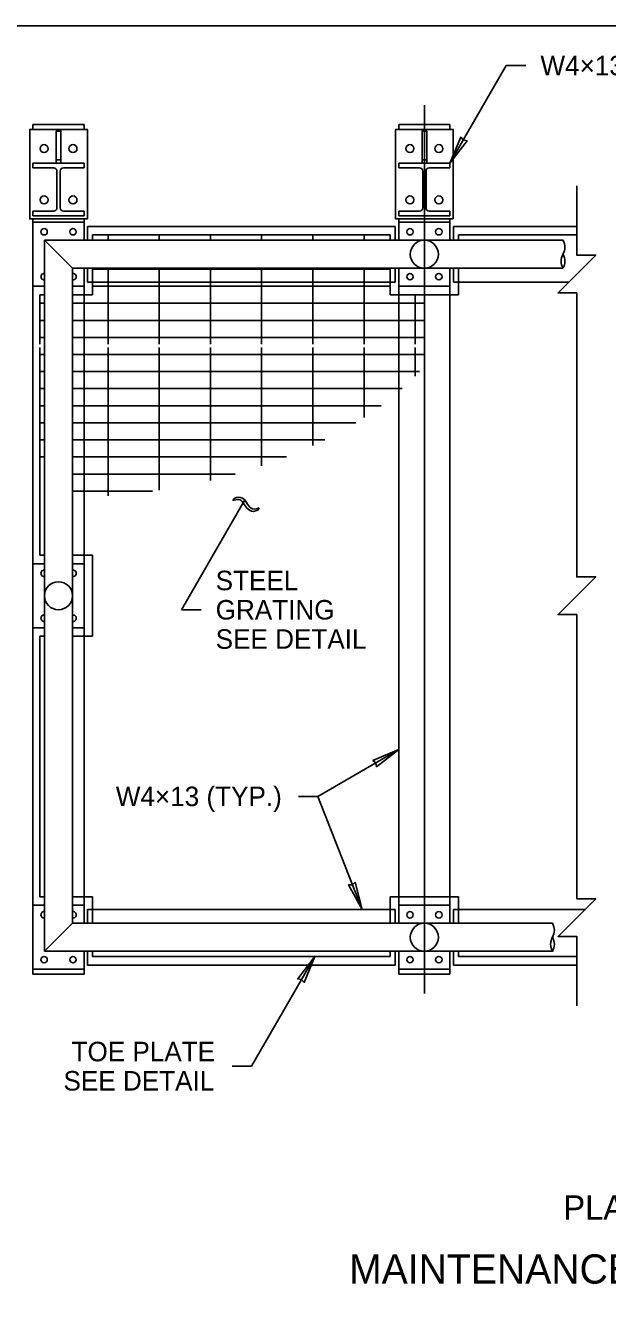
# Model space of a CAD drawing. Extents: x 99862 to 103151, y 100000 to 108076.
# Drawn here: x 100986 to 101463, y 101023 to 102076 of the extents above; entities that cross this region are included whole.
import ezdxf

# ---------------------------------------------------------------- set-up
doc = ezdxf.new("R2010")
doc.units = 0
for name, color, linetype in [('Level 1', 7, 'Continuous'), ('Level 13', 7, 'Continuous'), ('Level 15', 7, 'Continuous'), ('Level 20', 7, 'Continuous'), ('Level 36', 7, 'Continuous'), ('Level 4', 7, 'Continuous'), ('Level 5', 7, 'Continuous')]:
    doc.layers.add(name, color=color, linetype=linetype)

msp = doc.modelspace()

# ---------------------------------------------------------------- linework, layer by layer
at = {"layer": 'Level 1'}
msp.add_lwpolyline([(99862, 99999.5), (103151, 99999.5), (103151, 102075.5), (99862, 102075.5)], close=True, dxfattribs=at)
at = {"layer": 'Level 13'}
for p, q in [((100991.8, 101994.4), (101033.8, 101994.4)), ((100991.8, 101990.5), (100991.8, 101994.4)), ((101033.8, 101990.5), (101033.8, 101994.4)), ((101291.8, 101994.4), (101333.8, 101994.4)), ((101291.8, 101990.5), (101291.8, 101994.4)), ((101333.8, 101990.5), (101333.8, 101994.4)), ((101033.8, 101962.9), (100991.8, 101962.9)), ((100991.8, 101962.9), (100991.8, 101959)), ((100991.8, 101959), (101008.9, 101959)), ((101011.5, 101956.3), (101011.5, 101926.1)), ((101014.2, 101926.1), (101014.2, 101956.3)), ((101016.8, 101959), (101033.8, 101959)), ((101033.8, 101959), (101033.8, 101962.9)), ((101333.8, 101962.9), (101291.8, 101962.9)), ((101291.8, 101962.9), (101291.8, 101959)), ((101291.8, 101959), (101308.9, 101959)), ((101311.5, 101956.3), (101311.5, 101926.1)), ((101314.2, 101926.1), (101314.2, 101956.3)), ((101316.8, 101959), (101333.8, 101959)), ((101333.8, 101959), (101333.8, 101962.9)), ((101008.9, 101923.5), (100991.8, 101923.5)), ((100991.8, 101923.5), (100991.8, 101919.6)), ((101033.8, 101923.5), (101016.8, 101923.5)), ((101033.8, 101919.6), (101033.8, 101923.5)), ((101308.9, 101923.5), (101291.8, 101923.5)), ((101291.8, 101923.5), (101291.8, 101919.6)), ((101333.8, 101923.5), (101316.8, 101923.5)), ((101333.8, 101919.6), (101333.8, 101923.5)), ((100991.8, 101919.6), (101033.8, 101919.6)), ((100991.8, 101914.3), (101033.8, 101914.3)), ((101291.8, 101919.6), (101333.8, 101919.6)), ((101291.8, 101914.3), (101333.8, 101914.3)), ((101001.3, 101861.8), (100991.8, 101861.8)), ((101033.8, 101861.8), (101024.3, 101861.8)), ((101333.8, 101861.8), (101291.8, 101861.8)), ((100991.8, 101634.3), (101001.3, 101634.3)), ((101024.3, 101634.3), (101033.8, 101634.3)), ((101001.3, 101581.8), (100991.8, 101581.8)), ((101033.8, 101581.8), (101024.3, 101581.8)), ((100991.8, 101301.8), (100991.8, 101354.3)), ((100991.8, 101354.3), (101001.3, 101354.3)), ((101024.3, 101354.3), (101033.8, 101354.3)), ((101033.8, 101354.3), (101033.8, 101339.6)), ((101033.8, 101316.6), (101033.8, 101301.8)), ((101033.8, 101301.8), (100991.8, 101301.8))]:
    msp.add_line(p, q, dxfattribs=at)
for points in [[(101036.5, 101917), (100989.2, 101917), (100989.2, 101990.5), (101036.5, 101990.5)], [(101010.9, 101962.9), (101010.9, 101989.1), (101014.8, 101989.1), (101014.8, 101962.9)], [(101336.5, 101917), (101289.2, 101917), (101289.2, 101990.5), (101336.5, 101990.5)], [(101310.9, 101962.9), (101310.9, 101989.1), (101314.8, 101989.1), (101314.8, 101962.9)], [(101010.9, 101962.9), (101010.9, 101965.5), (101014.8, 101965.5), (101014.8, 101962.9)], [(101310.9, 101962.9), (101310.9, 101965.5), (101314.8, 101965.5), (101314.8, 101962.9)]]:
    msp.add_lwpolyline(points, close=True, dxfattribs=at)
for points in [[(101291.8, 101339.6), (101291.8, 101354.3), (101333.8, 101354.3), (101333.8, 101339.6)], [(101333.8, 101316.6), (101333.8, 101301.8), (101291.8, 101301.8), (101291.8, 101316.6)]]:
    msp.add_lwpolyline(points, dxfattribs=at)
for centre, radius in [((101001, 101974.7), 3.28), ((101024.7, 101974.7), 3.28), ((101301, 101974.7), 3.28), ((101324.7, 101974.7), 3.28), ((101001, 101932.7), 3.28), ((101024.7, 101932.7), 3.28), ((101301, 101932.7), 3.28), ((101324.7, 101932.7), 3.28), ((101001, 101906.5), 2.62), ((101024.7, 101906.5), 2.62), ((101301, 101906.5), 2.62), ((101324.7, 101906.5), 2.62), ((101301, 101869.7), 2.62), ((101324.7, 101869.7), 2.62), ((101301, 101346.5), 2.62), ((101324.7, 101346.5), 2.62), ((101001, 101309.7), 2.62), ((101024.7, 101309.7), 2.62), ((101301, 101309.7), 2.62), ((101324.7, 101309.7), 2.62)]:
    msp.add_circle(centre, radius, dxfattribs=at)
for centre, start, end in [((101008.9, 101956.3), 0, 90), ((101016.8, 101956.3), 90, 180), ((101308.9, 101956.3), 0, 90), ((101316.8, 101956.3), 90, 180), ((101008.9, 101926.1), 270, 360), ((101016.8, 101926.1), 180, 270), ((101308.9, 101926.1), 270, 360), ((101316.8, 101926.1), 180, 270), ((101001, 101869.7), 83.163, 276.837), ((101024.7, 101869.7), 263.1627, 96.8373), ((101001, 101626.5), 83.1632, 276.8368), ((101024.7, 101626.5), 263.1625, 96.8375), ((101001, 101589.7), 83.1632, 276.8368), ((101024.7, 101589.7), 263.1625, 96.8375), ((101001, 101346.5), 83.1632, 276.8368), ((101024.7, 101346.5), 263.1625, 96.8375)]:
    msp.add_arc(centre, 2.62, start, end, dxfattribs=at)
at = {"layer": 'Level 15'}
for p, q in [((101333.8, 101962.9), (101380, 102042.8)), ((101380, 102042.8), (101396, 102042.8)), ((101312.8, 101281.9), (101312.8, 102010.4)), ((101165.6, 101686.6), (101113.7, 101596.6)), ((101113.7, 101596.6), (101129.7, 101596.6)), ((101225.5, 101443.5), (101291.8, 101481.9)), ((101209.5, 101443.5), (101225.5, 101443.5)), ((101225.5, 101443.5), (101261.7, 101350.9)), ((101223, 101312.3), (101171.1, 101222.3)), ((101171.1, 101222.3), (101155.1, 101222.3))]:
    msp.add_line(p, q, dxfattribs=at)
for points in [[(101333.8, 101962.9), (101347.8, 101981.2), (101344.7, 101981.8), (101342.7, 101984.2)], [(101291.8, 101481.9), (101270.6, 101473), (101273, 101471), (101273.6, 101467.9)], [(101261.7, 101350.9), (101256.2, 101373.2), (101253.8, 101371.1), (101250.6, 101371)], [(101223, 101312.3), (101214.2, 101291), (101212.1, 101293.4), (101209, 101294)]]:
    msp.add_lwpolyline(points, close=True, dxfattribs=at)
msp.add_lwpolyline([(101437.8, 101271.9), (101437.8, 101328.8), (101422.4, 101328.8), (101453.3, 101359.7), (101437.8, 101359.7), (101437.8, 101592.6), (101422.4, 101592.6), (101453.3, 101623.6), (101437.8, 101623.6), (101437.8, 101856.4), (101422.4, 101856.4), (101453.3, 101887.4), (101437.8, 101887.4), (101437.8, 101944.2)], dxfattribs=at)
for centre, start, end in [((101416.5, 101893.8), 330, 30), ((101436.5, 101882.3), 150, 210), ((101416.5, 101882.3), 330, 30), ((101407.9, 101333.8), 330, 30), ((101427.8, 101322.3), 150, 210), ((101407.9, 101322.3), 330, 30)]:
    msp.add_arc(centre, 11.5, start, end, dxfattribs=at)
at = {"layer": 'Level 20'}
for p, q in [((101155.7, 101686.1), (101156.8, 101687.9)), ((101159.3, 101687), (101155.7, 101686.1)), ((101156.8, 101687.9), (101158.8, 101688.7)), ((101158.8, 101688.7), (101160.5, 101688.9)), ((101160.9, 101686.9), (101159.3, 101687)), ((101160.5, 101688.9), (101162.1, 101688.7)), ((101162.3, 101686.5), (101160.9, 101686.9)), ((101162.1, 101688.7), (101163.7, 101688.1)), ((101163.4, 101685.5), (101162.3, 101686.5)), ((101164.8, 101683.5), (101163.4, 101685.5)), ((101163.7, 101688.1), (101165.6, 101686.6)), ((101167.3, 101679.9), (101164.8, 101683.5)), ((101165.6, 101686.6), (101167.9, 101683.2)), ((101169.4, 101678.2), (101167.3, 101679.9)), ((101167.9, 101683.2), (101169.3, 101681.1)), ((101169.3, 101681.1), (101170.8, 101679.8)), ((101170.8, 101679.8), (101172, 101679.3)), ((101172, 101679.3), (101173.4, 101679.2)), ((101173.4, 101679.2), (101175.1, 101679.4)), ((101175.1, 101679.4), (101177.4, 101680.2)), ((101177.4, 101680.2), (101176.3, 101678.3)), ((101171, 101677.5), (101169.4, 101678.2)), ((101172.7, 101677.3), (101171, 101677.5)), ((101174.5, 101677.6), (101172.7, 101677.3)), ((101176.3, 101678.3), (101174.5, 101677.6))]:
    msp.add_line(p, q, dxfattribs=at)
at = {"layer": 'Level 36'}
for centre in [(101312.8, 101888.1), (101012.8, 101608.1), (101312.8, 101328.1)]:
    msp.add_circle(centre, 11.5, dxfattribs=at)
at = {"layer": 'Level 4'}
for p, q in [((100991.8, 101990.5), (100991.8, 101994.4)), ((100991.8, 101994.4), (101033.8, 101994.4)), ((101033.8, 101994.4), (101033.8, 101990.5)), ((101291.8, 101990.5), (101291.8, 101994.4)), ((101291.8, 101994.4), (101333.8, 101994.4)), ((101333.8, 101994.4), (101333.8, 101990.5)), ((100991.8, 101297.9), (100991.8, 101917)), ((101033.8, 101899.6), (101033.8, 101917)), ((101036.6, 101910.9), (101289, 101910.9)), ((101036.6, 101910.9), (101036.6, 101899.6)), ((101289, 101910.9), (101289, 101899.6)), ((101291.8, 101917), (101291.8, 101899.6)), ((101333.8, 101917), (101333.8, 101899.6)), ((101437.8, 101910.9), (101336.6, 101910.9)), ((101336.6, 101899.6), (101336.6, 101910.9)), ((101040.8, 101903.9), (101284.8, 101903.9)), ((101040.8, 101903.9), (101040.8, 101899.6)), ((101053.4, 101903.9), (101053.4, 101899.6)), ((101095.4, 101903.9), (101095.4, 101899.6)), ((101137.4, 101903.9), (101137.4, 101899.6)), ((101179.4, 101903.9), (101179.4, 101899.6)), ((101221.4, 101903.9), (101221.4, 101899.6)), ((101263.4, 101903.9), (101263.4, 101899.6)), ((101284.8, 101903.9), (101284.8, 101899.6)), ((101340.8, 101903.9), (101437.8, 101903.9)), ((101340.8, 101903.9), (101340.8, 101899.6)), ((101033.8, 101339.6), (101033.8, 101876.6)), ((101036.6, 101876.6), (101036.6, 101865.3)), ((101040.8, 101876.6), (101040.8, 101854.9)), ((101040.8, 101875.9), (101284.8, 101875.9)), ((101053.4, 101876.6), (101053.4, 101814.3)), ((101095.4, 101876.6), (101095.4, 101814.3)), ((101137.4, 101876.6), (101137.4, 101814.3)), ((101179.4, 101876.6), (101179.4, 101814.3)), ((101221.4, 101876.6), (101221.4, 101814.3)), ((101263.4, 101876.6), (101263.4, 101814.3)), ((101284.8, 101876.6), (101284.8, 101854.9)), ((101289, 101876.6), (101289, 101865.3)), ((101291.8, 101876.6), (101291.8, 101339.6)), ((101333.8, 101876.6), (101333.8, 101339.6)), ((101336.6, 101865.3), (101336.6, 101876.6)), ((101340.8, 101876.6), (101340.8, 101854.9)), ((101036.6, 101865.3), (101289, 101865.3)), ((101040.8, 101861.9), (101284.8, 101861.9)), ((101431.2, 101865.3), (101336.6, 101865.3)), ((100997.4, 101854.9), (100997.4, 101814.3)), ((100997.4, 101854.9), (101001.3, 101854.9)), ((100997.4, 101847.9), (101001.3, 101847.9)), ((101024.3, 101854.9), (101040.8, 101854.9)), ((101024.3, 101847.9), (101312.8, 101847.9)), ((101340.8, 101854.9), (101284.8, 101854.9)), ((101305.4, 101854.9), (101305.4, 101814.3)), ((100997.4, 101833.9), (101001.3, 101833.9)), ((101024.3, 101833.9), (101312.8, 101833.9)), ((100997.4, 101819.9), (101001.3, 101819.9)), ((101024.3, 101819.9), (101312.8, 101819.9)), ((100997.4, 101811.5), (100997.4, 101641.3)), ((100997.4, 101805.9), (101001.3, 101805.9)), ((101024.3, 101805.9), (101312.8, 101805.9)), ((101053.4, 101811.5), (101053.4, 101690.1)), ((101095.4, 101811.5), (101095.4, 101694.7)), ((101137.4, 101811.5), (101137.4, 101702.7)), ((101179.4, 101811.5), (101179.4, 101714.6)), ((101221.4, 101811.5), (101221.4, 101731.2)), ((101263.4, 101811.5), (101263.4, 101754.2)), ((101305.4, 101811.5), (101305.4, 101788.2)), ((100997.4, 101791.9), (101001.3, 101791.9)), ((101024.3, 101791.9), (101308.9, 101791.9)), ((100997.4, 101777.9), (101001.3, 101777.9)), ((101024.3, 101777.9), (101294.6, 101777.9)), ((100997.4, 101763.9), (101001.3, 101763.9)), ((101024.3, 101763.9), (101277.3, 101763.9)), ((100997.4, 101749.9), (101001.3, 101749.9)), ((101024.3, 101749.9), (101256.6, 101749.9)), ((100997.4, 101735.9), (101001.3, 101735.9)), ((101024.3, 101735.9), (101231.3, 101735.9)), ((100997.4, 101721.9), (101001.3, 101721.9)), ((101024.3, 101721.9), (101199.7, 101721.9)), ((101024.3, 101707.9), (101157.7, 101707.9)), ((101024.3, 101693.9), (101089.9, 101693.9)), ((100997.4, 101641.3), (101001.3, 101641.3)), ((101024.3, 101641.3), (101040.8, 101641.3)), ((101040.8, 101574.9), (101040.8, 101641.3)), ((100997.4, 101361.3), (100997.4, 101574.9)), ((100997.4, 101574.9), (101001.3, 101574.9)), ((101024.3, 101574.9), (101040.8, 101574.9)), ((100997.4, 101361.3), (101001.3, 101361.3)), ((101024.3, 101361.3), (101040.8, 101361.3)), ((101040.8, 101339.6), (101040.8, 101361.3)), ((101340.8, 101361.3), (101284.8, 101361.3)), ((101284.8, 101339.6), (101284.8, 101361.3)), ((101340.8, 101339.6), (101340.8, 101361.3)), ((101036.6, 101350.9), (101289, 101350.9)), ((101036.6, 101339.6), (101036.6, 101350.9)), ((101289, 101339.6), (101289, 101350.9)), ((101336.6, 101339.6), (101336.6, 101350.9)), ((101444.5, 101350.9), (101336.6, 101350.9)), ((101033.8, 101297.9), (101033.8, 101316.6)), ((101036.6, 101305.3), (101036.6, 101316.6)), ((101040.8, 101312.3), (101040.8, 101316.6)), ((101040.8, 101312.3), (101284.8, 101312.3)), ((101284.8, 101312.3), (101284.8, 101316.6)), ((101289, 101305.3), (101289, 101316.6)), ((101291.8, 101316.6), (101291.8, 101297.9)), ((101333.8, 101316.6), (101333.8, 101297.9)), ((101336.6, 101305.3), (101336.6, 101316.6)), ((101340.8, 101312.3), (101340.8, 101316.6)), ((101340.8, 101312.3), (101437.8, 101312.3)), ((101036.6, 101305.3), (101289, 101305.3)), ((101437.8, 101305.3), (101336.6, 101305.3)), ((100991.8, 101297.9), (101033.8, 101297.9)), ((101291.8, 101297.9), (101333.8, 101297.9))]:
    msp.add_line(p, q, dxfattribs=at)
at = {"layer": 'Level 5'}
for p, q in [((101024.3, 101876.6), (101001.3, 101899.6)), ((101001.3, 101899.6), (101426.5, 101899.6)), ((101001.3, 101316.6), (101001.3, 101899.6)), ((101024.3, 101876.6), (101426.4, 101876.6)), ((101024.3, 101339.6), (101024.3, 101876.6)), ((101024.3, 101339.6), (101001.3, 101316.6)), ((101024.3, 101339.6), (101417.8, 101339.6)), ((101001.3, 101316.6), (101417.8, 101316.6))]:
    msp.add_line(p, q, dxfattribs=at)

# ---------------------------------------------------------------- texts
at = {"layer": 'Level 20'}
for s, height, p in [('W4×13 (TYP.)', 16, (101408, 102034.8)), ('STEEL', 16, (101141.7, 101612.6)), ('GRATING', 16, (101141.7, 101588.6)), ('SEE DETAIL', 16, (101141.7, 101564.6)), ('W4×13 (TYP.)', 16, (101059.8, 101435.6)), ('TOE PLATE', 16, (101023.5, 101226.4)), ('SEE DETAIL', 16, (101016.9, 101202.4)), ('PLAN', 20, (101426.8, 101096.5)), ('MAINTENANCE WALKWAY', 24, (101251.1, 101044.1))]:
    msp.add_text(s, height=height, dxfattribs=at).set_placement(p)

doc.saveas('drawing.dxf')
